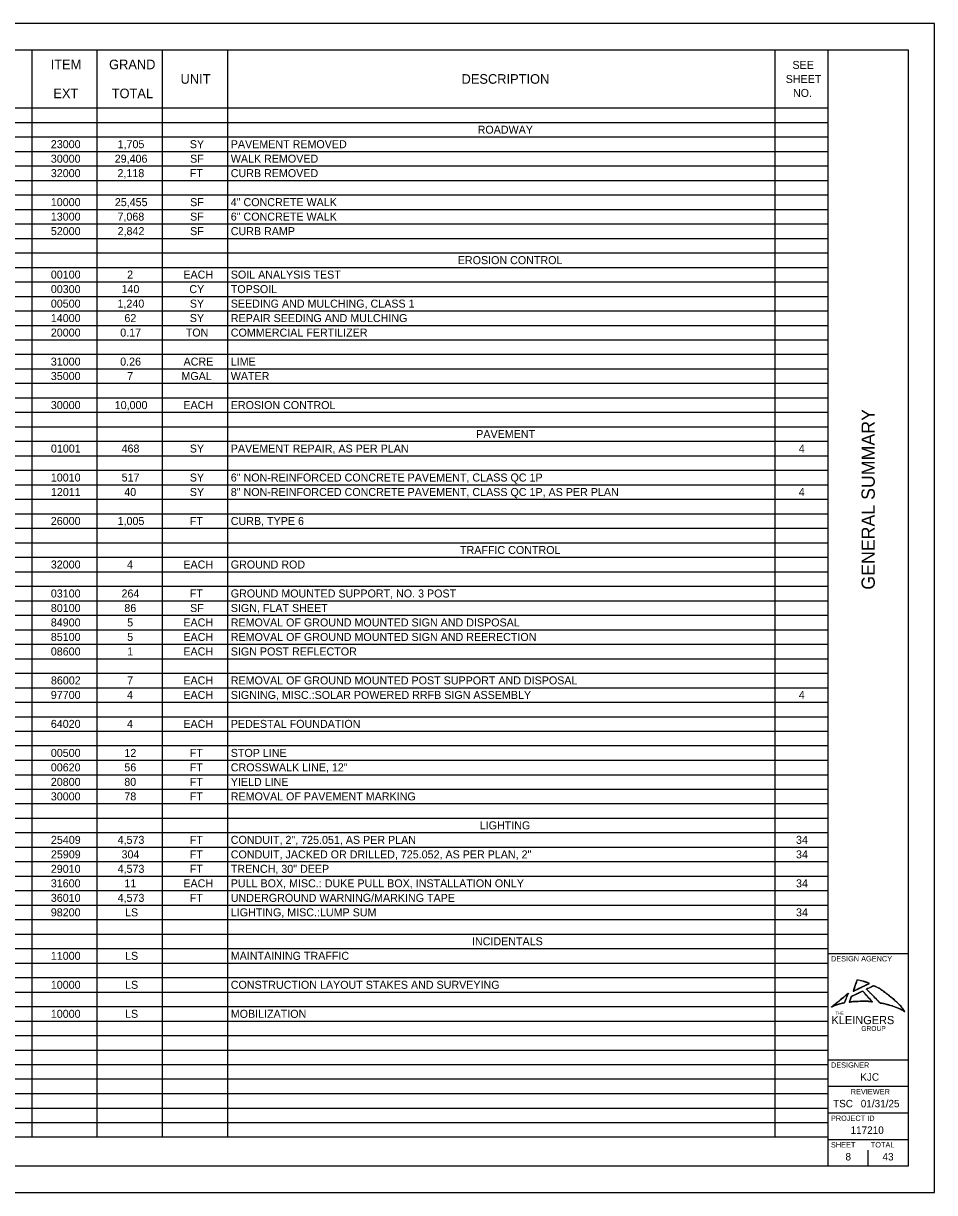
# Model space of a CAD drawing. Extents: x 0 to 34, y 0 to 22.
# Drawn here: x 16.86 to 34, y 0 to 22 of the extents above; entities that cross this region are included whole.
import ezdxf

# ---------------------------------------------------------------- set-up
doc = ezdxf.new("R2010")
doc.units = 0
for name, color, linetype in [('Default', 7, 'Continuous'), ('SH_Border', 7, 'Continuous'), ('SH_Cut_Line', 7, 'Continuous'), ('SH_Data', 7, 'Continuous')]:
    doc.layers.add(name, color=color, linetype=linetype)

msp = doc.modelspace()

# ---------------------------------------------------------------- linework, layer by layer
at = {"layer": 'Default'}
for p, q in [((1.5, 21.5), (31.993, 21.5)), ((17.017, 21.5), (17.017, 1.047)), ((18.244, 21.5), (18.244, 1.047)), ((19.471, 21.5), (19.471, 1.047)), ((20.698, 21.5), (20.698, 1.047)), ((30.994, 21.5), (30.994, 1.047)), ((31.993, 21.5), (31.993, 1.047)), ((1.5, 20.409), (31.993, 20.409)), ((1.5, 20.136), (31.993, 20.136)), ((1.5, 19.864), (31.993, 19.864)), ((1.5, 19.591), (31.993, 19.591)), ((1.5, 19.318), (31.993, 19.318)), ((1.5, 19.046), (31.993, 19.046)), ((1.5, 18.773), (31.993, 18.773)), ((1.5, 18.5), (31.993, 18.5)), ((1.5, 18.227), (31.993, 18.227)), ((1.5, 17.955), (31.993, 17.955)), ((1.5, 17.682), (31.993, 17.682)), ((1.5, 17.409), (31.993, 17.409)), ((1.5, 17.137), (31.993, 17.137)), ((1.5, 16.864), (31.993, 16.864)), ((1.5, 16.591), (31.993, 16.591)), ((1.5, 16.318), (31.993, 16.318)), ((1.5, 16.046), (31.993, 16.046)), ((1.5, 15.773), (31.993, 15.773)), ((1.5, 15.5), (31.993, 15.5)), ((1.5, 15.228), (31.993, 15.228)), ((1.5, 14.955), (31.993, 14.955)), ((1.5, 14.682), (31.993, 14.682)), ((1.5, 14.41), (31.993, 14.41)), ((1.5, 14.137), (31.993, 14.137)), ((1.5, 13.864), (31.993, 13.864)), ((1.5, 13.591), (31.993, 13.591)), ((1.5, 13.319), (31.993, 13.319)), ((1.5, 13.046), (31.993, 13.046)), ((1.5, 12.773), (31.993, 12.773)), ((1.5, 12.501), (31.993, 12.501)), ((1.5, 12.228), (31.993, 12.228)), ((1.5, 11.955), (31.993, 11.955)), ((1.5, 11.682), (31.993, 11.682)), ((1.5, 11.41), (31.993, 11.41)), ((1.5, 11.137), (31.993, 11.137)), ((1.5, 10.864), (31.993, 10.864)), ((1.5, 10.592), (31.993, 10.592)), ((1.5, 10.319), (31.993, 10.319)), ((1.5, 10.046), (31.993, 10.046)), ((1.5, 9.773), (31.993, 9.773)), ((1.5, 9.501), (31.993, 9.501)), ((1.5, 9.228), (31.993, 9.228)), ((1.5, 8.955), (31.993, 8.955)), ((1.5, 8.683), (31.993, 8.683)), ((1.5, 8.41), (31.993, 8.41)), ((1.5, 8.137), (31.993, 8.137)), ((1.5, 7.864), (31.993, 7.864)), ((1.5, 7.592), (31.993, 7.592)), ((1.5, 7.319), (31.993, 7.319)), ((1.5, 7.046), (31.993, 7.046)), ((1.5, 6.774), (31.993, 6.774)), ((1.5, 6.501), (31.993, 6.501)), ((1.5, 6.228), (31.993, 6.228)), ((1.5, 5.955), (31.993, 5.955)), ((1.5, 5.683), (31.993, 5.683)), ((1.5, 5.41), (31.993, 5.41)), ((1.5, 5.137), (31.993, 5.137)), ((1.5, 4.865), (31.993, 4.865)), ((1.5, 4.592), (31.993, 4.592)), ((1.5, 4.319), (31.993, 4.319)), ((1.5, 4.046), (31.993, 4.046)), ((1.5, 3.774), (31.993, 3.774)), ((1.5, 3.501), (31.993, 3.501)), ((1.5, 3.228), (31.993, 3.228)), ((1.5, 2.956), (31.993, 2.956)), ((1.5, 2.683), (31.993, 2.683)), ((1.5, 2.41), (31.993, 2.41)), ((1.5, 2.138), (31.993, 2.138)), ((1.5, 1.865), (31.993, 1.865)), ((1.5, 1.592), (31.993, 1.592)), ((1.5, 1.319), (31.993, 1.319)), ((1.5, 1.047), (31.993, 1.047))]:
    msp.add_line(p, q, dxfattribs=at)
for points, degree in [([(32.542, 4.004), (32.542, 4.004), (32.47, 3.788), (32.47, 3.788)], 2), ([(32.772, 3.935), (32.772, 3.935), (32.722, 3.958), (32.655, 3.979), (32.588, 3.999), (32.542, 4.004), (32.542, 4.004), (32.542, 4.004), (32.47, 3.788), (32.47, 3.788), (32.47, 3.788), (32.772, 3.935), (32.772, 3.935)], 3), ([(32.772, 3.935), (32.772, 3.935), (32.722, 3.958), (32.655, 3.979)], 2), ([(32.379, 3.752), (32.379, 3.752), (32.061, 3.492), (32.061, 3.492)], 2), ([(32.379, 3.752), (32.379, 3.752), (32.061, 3.492), (32.061, 3.492), (32.061, 3.492), (32.133, 3.529), (32.21, 3.55), (32.28, 3.569), (32.303, 3.572), (32.303, 3.572), (32.303, 3.572), (32.379, 3.752), (32.379, 3.752)], 3), ([(32.303, 3.572), (32.303, 3.572), (32.379, 3.752), (32.379, 3.752)], 2), ([(32.648, 3.793), (32.648, 3.793), (32.83, 3.589), (32.83, 3.589), (32.83, 3.589), (32.734, 3.604), (32.602, 3.6), (32.455, 3.595), (32.396, 3.584), (32.396, 3.584), (32.396, 3.584), (32.434, 3.691), (32.434, 3.691), (32.434, 3.691), (32.648, 3.793), (32.648, 3.793)], 3), ([(32.434, 3.691), (32.434, 3.691), (32.648, 3.793), (32.648, 3.793)], 2), ([(32.47, 3.788), (32.47, 3.788), (32.772, 3.935), (32.772, 3.935)], 2), ([(32.648, 3.793), (32.648, 3.793), (32.83, 3.589), (32.83, 3.589)], 2), ([(33.2, 3.512), (33.079, 3.551), (32.978, 3.567), (32.978, 3.567), (32.978, 3.567), (32.717, 3.827), (32.717, 3.827), (32.717, 3.827), (32.855, 3.894), (32.855, 3.894), (32.855, 3.894), (32.985, 3.834), (33.142, 3.708), (33.348, 3.542), (33.438, 3.405), (33.438, 3.405), (33.438, 3.405), (33.351, 3.463), (33.2, 3.512)], 3), ([(32.717, 3.827), (32.717, 3.827), (32.855, 3.894), (32.855, 3.894)], 2), ([(32.978, 3.567), (32.978, 3.567), (32.717, 3.827), (32.717, 3.827)], 2), ([(32.855, 3.894), (32.855, 3.894), (32.985, 3.834), (33.142, 3.708)], 2), ([(32.061, 3.492), (32.061, 3.492), (32.133, 3.529), (32.21, 3.55)], 2), ([(32.21, 3.55), (32.28, 3.569), (32.303, 3.572), (32.303, 3.572)], 2), ([(32.396, 3.584), (32.396, 3.584), (32.434, 3.691), (32.434, 3.691)], 2), ([(32.602, 3.6), (32.455, 3.595), (32.396, 3.584), (32.396, 3.584)], 2), ([(32.83, 3.589), (32.83, 3.589), (32.734, 3.604), (32.602, 3.6)], 2), ([(33.2, 3.512), (33.079, 3.551), (32.978, 3.567), (32.978, 3.567)], 2), ([(33.142, 3.708), (33.348, 3.542), (33.438, 3.405), (33.438, 3.405)], 2), ([(33.438, 3.405), (33.438, 3.405), (33.351, 3.463), (33.2, 3.512)], 2)]:
    msp.add_open_spline(points, degree=degree, dxfattribs=at)
at = {"layer": 'SH_Border'}
for p, q in [((32, 0.5), (32, 21.5)), ((32, 4.5), (33.5, 4.5)), ((32, 2.5), (33.5, 2.5)), ((32, 2), (33.5, 2)), ((32, 1.5), (33.5, 1.5)), ((32, 1), (33.5, 1))]:
    msp.add_line(p, q, dxfattribs=at)
msp.add_lwpolyline([(1.5, 21.5), (33.5, 21.5), (33.5, 0.5), (1.5, 0.5)], close=True, dxfattribs=at)
at = {"layer": 'SH_Cut_Line'}
msp.add_lwpolyline([(0, 0), (34, 0), (34, 22), (0, 22)], close=True, dxfattribs=at)
at = {"layer": 'SH_Data'}
for p, q in [((32.75, 3.5), (32.75, 3.5)), ((32.375, 0.675), (32.375, 0.675)), ((32.75, 0.5), (32.75, 0.8))]:
    msp.add_line(p, q, dxfattribs=at)

# ---------------------------------------------------------------- texts
at = {"layer": 'Default'}
for s, height, p in [('ITEM', 0.1806, (17.373, 21.137)), ('GRAND', 0.1806, (18.472, 21.137)), ('SEE ', 0.1505, (31.326, 21.143)), ('UNIT', 0.1806, (19.816, 20.864)), ('DESCRIPTION', 0.18064, (25.102, 20.864)), ('SHEET ', 0.1505, (31.199, 20.879)), ('EXT', 0.1806, (17.424, 20.592)), ('TOTAL', 0.1806, (18.521, 20.592)), ('NO.', 0.1505, (31.336, 20.616)), ('ROADWAY', 0.1505, (25.405, 19.925)), ('23000', 0.1505, (17.376, 19.652)), ('1,705', 0.1505, (18.632, 19.652)), ('SY', 0.1505, (19.991, 19.652)), ('PAVEMENT REMOVED', 0.15054, (20.761, 19.652)), ('30000', 0.1505, (17.376, 19.379)), ('29,406', 0.1505, (18.578, 19.379)), ('SF', 0.1505, (19.996, 19.379)), ('WALK REMOVED', 0.15054, (20.761, 19.379)), ('32000', 0.1505, (17.376, 19.107)), ('2,118', 0.1505, (18.63, 19.107)), ('FT', 0.1505, (19.989, 19.107)), ('CURB REMOVED', 0.15054, (20.761, 19.107)), ('10000', 0.1505, (17.376, 18.561)), ('25,455', 0.1505, (18.58, 18.561)), ('SF', 0.1505, (19.996, 18.561)), ('4" CONCRETE WALK', 0.15054, (20.761, 18.561)), ('13000', 0.1505, (17.376, 18.289)), ('7,068', 0.1505, (18.63, 18.289)), ('SF', 0.1505, (19.996, 18.289)), ('6" CONCRETE WALK', 0.15054, (20.761, 18.289)), ('52000', 0.1505, (17.376, 18.016)), ('2,842', 0.1505, (18.632, 18.016)), ('SF', 0.1505, (19.996, 18.016)), ('CURB RAMP', 0.1505, (20.761, 18.016)), ('EROSION CONTROL', 0.15054, (25.031, 17.47)), ('00100', 0.1505, (17.376, 17.198)), ('2', 0.151, (18.812, 17.198)), ('EACH', 0.1505, (19.869, 17.198)), ('SOIL ANALYSIS TEST', 0.15054, (20.761, 17.198)), ('00300', 0.1505, (17.376, 16.925)), ('140', 0.1505, (18.706, 16.925)), ('CY', 0.1505, (19.982, 16.925)), ('TOPSOIL', 0.1505, (20.761, 16.925)), ('00500', 0.1505, (17.376, 16.652)), ('1,240', 0.1505, (18.63, 16.652)), ('SY', 0.1505, (19.991, 16.652)), ('SEEDING AND MULCHING, CLASS 1', 0.15054, (20.761, 16.652)), ('14000', 0.1505, (17.376, 16.38)), ('62', 0.1505, (18.76, 16.38)), ('SY', 0.1505, (19.991, 16.38)), ('REPAIR SEEDING AND MULCHING', 0.15054, (20.761, 16.38)), ('20000', 0.1505, (17.376, 16.107)), ('0.17', 0.1505, (18.682, 16.107)), ('TON', 0.1505, (19.914, 16.107)), ('COMMERCIAL FERTILIZER', 0.15054, (20.761, 16.107)), ('31000', 0.1505, (17.376, 15.561)), ('0.26', 0.1505, (18.681, 15.561)), ('ACRE', 0.1505, (19.873, 15.561)), ('LIME', 0.1505, (20.761, 15.561)), ('35000', 0.1505, (17.376, 15.289)), ('7', 0.151, (18.811, 15.289)), ('MGAL', 0.1505, (19.833, 15.289)), ('WATER', 0.1505, (20.761, 15.289)), ('30000', 0.1505, (17.376, 14.743)), ('10,000', 0.1505, (18.578, 14.743)), ('EACH', 0.1505, (19.869, 14.743)), ('EROSION CONTROL', 0.15054, (20.761, 14.743)), ('PAVEMENT', 0.1505, (25.378, 14.198)), ('01001', 0.1505, (17.378, 13.925)), ('468', 0.1505, (18.707, 13.925)), ('SY', 0.1505, (19.991, 13.925)), ('PAVEMENT REPAIR, AS PER PLAN', 0.15054, (20.761, 13.925)), ('4', 0.151, (31.445, 13.925)), ('10010', 0.1505, (17.376, 13.38)), ('517', 0.1505, (18.708, 13.38)), ('SY', 0.1505, (19.991, 13.38)), ('6" NON-REINFORCED CONCRETE PAVEMENT, CLASS QC 1P', 0.15054, (20.761, 13.38)), ('12011', 0.1505, (17.378, 13.107)), ('40', 0.1505, (18.758, 13.107)), ('SY', 0.1505, (19.991, 13.107)), ('8" NON-REINFORCED CONCRETE PAVEMENT, CLASS QC 1P, AS PER PLAN', 0.15054, (20.761, 13.107)), ('4', 0.151, (31.445, 13.107)), ('26000', 0.1505, (17.376, 12.562)), ('1,005', 0.1505, (18.632, 12.562)), ('FT', 0.1505, (19.989, 12.562)), ('CURB, TYPE 6', 0.15054, (20.761, 12.562)), ('TRAFFIC CONTROL', 0.15054, (25.073, 12.016)), ('32000', 0.1505, (17.376, 11.743)), ('4', 0.151, (18.809, 11.743)), ('EACH', 0.1505, (19.869, 11.743)), ('GROUND ROD', 0.1505, (20.761, 11.743)), ('03100', 0.1505, (17.376, 11.198)), ('264', 0.1505, (18.706, 11.198)), ('FT', 0.1505, (19.989, 11.198)), ('GROUND MOUNTED SUPPORT, NO. 3 POST', 0.15054, (20.761, 11.198)), ('80100', 0.1505, (17.376, 10.925)), ('86', 0.1505, (18.759, 10.925)), ('SF', 0.1505, (19.996, 10.925)), ('SIGN, FLAT SHEET', 0.15054, (20.761, 10.925)), ('84900', 0.1505, (17.376, 10.653)), ('5', 0.151, (18.812, 10.653)), ('EACH', 0.1505, (19.869, 10.653)), ('REMOVAL OF GROUND MOUNTED SIGN AND DISPOSAL', 0.15054, (20.761, 10.653)), ('85100', 0.1505, (17.376, 10.38)), ('5', 0.151, (18.812, 10.38)), ('EACH', 0.1505, (19.869, 10.38)), ('REMOVAL OF GROUND MOUNTED SIGN AND REERECTION', 0.15054, (20.761, 10.38)), ('08600', 0.1505, (17.376, 10.107)), ('1', 0.151, (18.812, 10.107)), ('EACH', 0.1505, (19.869, 10.107)), ('SIGN POST REFLECTOR', 0.15054, (20.761, 10.107)), ('86002', 0.1505, (17.378, 9.562)), ('7', 0.151, (18.811, 9.562)), ('EACH', 0.1505, (19.869, 9.562)), ('REMOVAL OF GROUND MOUNTED POST SUPPORT AND DISPOSAL', 0.15054, (20.761, 9.562)), ('97700', 0.1505, (17.376, 9.289)), ('4', 0.151, (18.809, 9.289)), ('EACH', 0.1505, (19.869, 9.289)), ('SIGNING, MISC.:SOLAR POWERED RRFB SIGN ASSEMBLY', 0.15054, (20.761, 9.289)), ('4', 0.151, (31.445, 9.289)), ('64020', 0.1505, (17.376, 8.744)), ('4', 0.151, (18.809, 8.744)), ('EACH', 0.1505, (19.869, 8.744)), ('PEDESTAL FOUNDATION', 0.15054, (20.761, 8.744)), ('00500', 0.1505, (17.376, 8.198)), ('12', 0.1505, (18.76, 8.198)), ('FT', 0.1505, (19.989, 8.198)), ('STOP LINE', 0.1505, (20.761, 8.198)), ('00620', 0.1505, (17.376, 7.926)), ('56', 0.1505, (18.759, 7.926)), ('FT', 0.1505, (19.989, 7.926)), ('CROSSWALK LINE, 12"', 0.15054, (20.761, 7.926)), ('20800', 0.1505, (17.376, 7.653)), ('80', 0.1505, (18.758, 7.653)), ('FT', 0.1505, (19.989, 7.653)), ('YIELD LINE', 0.1505, (20.761, 7.653)), ('30000', 0.1505, (17.376, 7.38)), ('78', 0.1505, (18.759, 7.38)), ('FT', 0.1505, (19.989, 7.38)), ('REMOVAL OF PAVEMENT MARKING', 0.15054, (20.761, 7.38)), ('LIGHTING', 0.1505, (25.444, 6.835)), ('25409', 0.1505, (17.378, 6.562)), ('4,573', 0.1505, (18.632, 6.562)), ('FT', 0.1505, (19.989, 6.562)), ('CONDUIT, 2", 725.051, AS PER PLAN', 0.15054, (20.761, 6.562)), ('34', 0.1505, (31.393, 6.562)), ('25909', 0.1505, (17.378, 6.289)), ('304', 0.1505, (18.706, 6.289)), ('FT', 0.1505, (19.989, 6.289)), ('CONDUIT, JACKED OR DRILLED, 725.052, AS PER PLAN, 2"', 0.15054, (20.761, 6.289)), ('34', 0.1505, (31.393, 6.289)), ('29010', 0.1505, (17.376, 6.017)), ('4,573', 0.1505, (18.632, 6.017)), ('FT', 0.1505, (19.989, 6.017)), ('TRENCH, 30" DEEP', 0.15054, (20.761, 6.017)), ('31600', 0.1505, (17.376, 5.744)), ('11', 0.1505, (18.76, 5.744)), ('EACH', 0.1505, (19.869, 5.744)), ('PULL BOX, MISC.: DUKE PULL BOX, INSTALLATION ONLY', 0.15054, (20.761, 5.744)), ('34', 0.1505, (31.393, 5.744)), ('36010', 0.1505, (17.376, 5.471)), ('4,573', 0.1505, (18.632, 5.471)), ('FT', 0.1505, (19.989, 5.471)), ('UNDERGROUND WARNING/MARKING TAPE', 0.15054, (20.761, 5.471)), ('98200', 0.1505, (17.376, 5.198)), ('LS', 0.1505, (18.772, 5.198)), ('LIGHTING, MISC.:LUMP SUM', 0.15054, (20.761, 5.198)), ('34', 0.1505, (31.393, 5.198)), ('INCIDENTALS', 0.15054, (25.298, 4.653)), ('11000', 0.1505, (17.376, 4.38)), ('LS', 0.1505, (18.772, 4.38)), ('MAINTAINING TRAFFIC', 0.15054, (20.761, 4.38)), ('10000', 0.1505, (17.376, 3.835)), ('LS', 0.1505, (18.772, 3.835)), ('CONSTRUCTION LAYOUT STAKES AND SURVEYING', 0.15054, (20.761, 3.835)), ('10000', 0.1505, (17.376, 3.289)), ('LS', 0.1505, (18.772, 3.289)), ('MOBILIZATION', 0.15054, (20.761, 3.289)), ('KLEINGERS', 0.1542, (32.061, 3.17)), ('THE', 0.0561, (32.135, 3.349)), ('GROUP', 0.0911, (32.62, 3.042))]:
    msp.add_text(s, height=height, dxfattribs=at).set_placement(p)
at = {"layer": 'SH_Data'}
msp.add_text('GENERAL SUMMARY', height=0.25, rotation=90, dxfattribs=at).set_placement((32.875, 11.344))
for s, height, p in [('DESIGN AGENCY', 0.1, (32.05, 4.35)), ('DESIGNER', 0.1, (32.05, 2.35)), ('KJC', 0.14, (32.602, 2.105)), ('REVIEWER', 0.1, (32.422, 1.85)), ('TSC', 0.14, (32.09, 1.605)), ('01/31/25', 0.14, (32.611, 1.605)), ('PROJECT ID', 0.1, (32.05, 1.35)), ('117210', 0.14, (32.419, 1.105)), ('SHEET', 0.1, (32.05, 0.85)), ('TOTAL', 0.1, (32.8, 0.85)), ('8', 0.14, (32.324, 0.605)), ('43', 0.14, (33.02, 0.605))]:
    msp.add_text(s, height=height, dxfattribs=at).set_placement(p)

doc.saveas('drawing.dxf')
